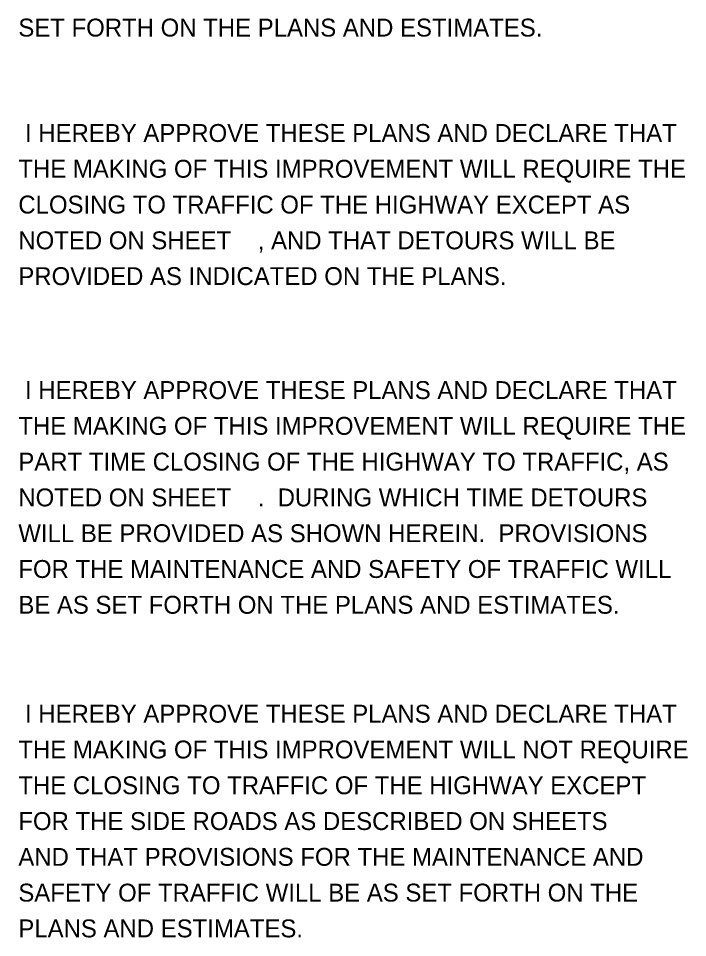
# Model space of a CAD drawing. Extents: x -15 to 405, y -40 to 87.
# Drawn here: x 37.06 to 42.29, y 3.93 to 11.12 of the extents above; entities that cross this region are included whole.
import ezdxf

# ---------------------------------------------------------------- set-up
doc = ezdxf.new("R2010")
doc.units = 0
doc.layers.add('GM_X_Township', color=7, linetype='Continuous')

msp = doc.modelspace()

# ---------------------------------------------------------------- texts
at = {"layer": 'GM_X_Township'}
for s, p in [('SET FORTH ON THE PLANS AND ESTIMATES.', (37.0563, 10.9809)), (' I HEREBY APPROVE THESE PLANS AND DECLARE THAT', (37.0563, 10.1562)), ('THE MAKING OF THIS IMPROVEMENT WILL REQUIRE THE', (37.0563, 9.8762)), ('CLOSING TO TRAFFIC OF THE HIGHWAY EXCEPT AS', (37.0563, 9.5962)), ('NOTED ON SHEET    , AND THAT DETOURS WILL BE', (37.0563, 9.3162)), ('PROVIDED AS INDICATED ON THE PLANS.', (37.0563, 9.0362)), (' I HEREBY APPROVE THESE PLANS AND DECLARE THAT', (37.0563, 8.1445)), ('THE MAKING OF THIS IMPROVEMENT WILL REQUIRE THE', (37.0563, 7.8645)), ('PART TIME CLOSING OF THE HIGHWAY TO TRAFFIC, AS', (37.0563, 7.5845)), ('NOTED ON SHEET    .  DURING WHICH TIME DETOURS', (37.0563, 7.3045)), ('WILL BE PROVIDED AS SHOWN HEREIN.  PROVISIONS', (37.0563, 7.0245)), ('FOR THE MAINTENANCE AND SAFETY OF TRAFFIC WILL', (37.0563, 6.7445)), ('BE AS SET FORTH ON THE PLANS AND ESTIMATES.', (37.0563, 6.4645)), (' I HEREBY APPROVE THESE PLANS AND DECLARE THAT', (37.0563, 5.6122)), ('THE MAKING OF THIS IMPROVEMENT WILL NOT REQUIRE', (37.0563, 5.3322)), ('THE CLOSING TO TRAFFIC OF THE HIGHWAY EXCEPT', (37.0563, 5.0522)), ('FOR THE SIDE ROADS AS DESCRIBED ON SHEETS    ', (37.0563, 4.7722)), ('AND THAT PROVISIONS FOR THE MAINTENANCE AND', (37.0563, 4.4922)), ('SAFETY OF TRAFFIC WILL BE AS SET FORTH ON THE', (37.0563, 4.2122)), ('PLANS AND ESTIMATES.', (37.0563, 3.9322))]:
    msp.add_text(s, height=0.14, dxfattribs=at).set_placement(p)

doc.saveas('drawing.dxf')
